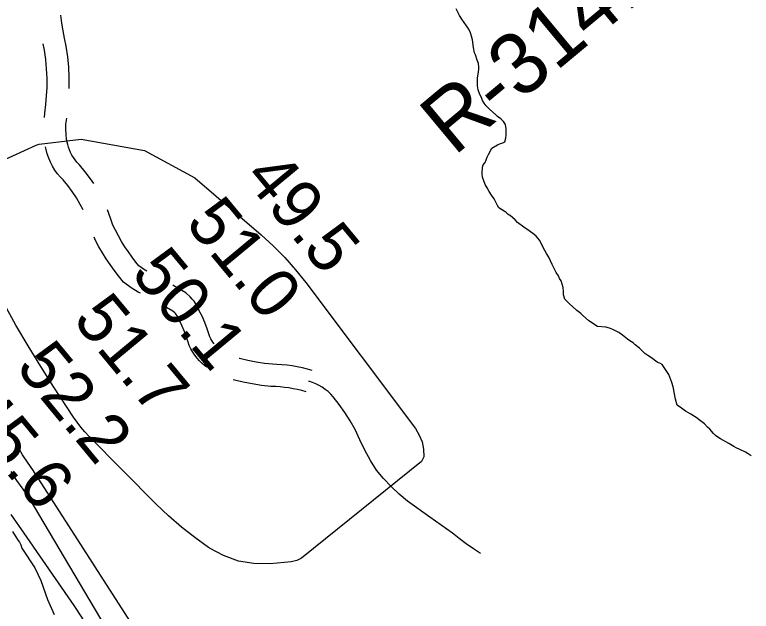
# Model space of a CAD drawing. Extents: x 3172231 to 3210228, y 940198 to 965780.
# Drawn here: x 3193133 to 3194127, y 949300 to 950105 of the extents above; entities that cross this region are included whole.
import ezdxf

# ---------------------------------------------------------------- set-up
doc = ezdxf.new("R2010")
doc.units = 0
for name, color, linetype in [('V-RIVR-RANG', 7, 'Continuous'), ('V-RIVR-RANG-IDEN', 7, 'Continuous'), ('V-ROAD-CNTR', 7, 'Continuous'), ('V-SITE-VEGE', 7, 'Continuous'), ('V-TOPO-MAJR', 7, 'Continuous'), ('V-TOPO-MINR', 7, 'Continuous'), ('V-TOPO-SHOR', 7, 'Continuous')]:
    doc.layers.add(name, color=color, linetype=linetype)

msp = doc.modelspace()

# ---------------------------------------------------------------- linework, layer by layer
at = {"layer": 'V-ROAD-CNTR'}
msp.add_line((3193530.228, 949610.409), (3193530.496, 949610.682), dxfattribs=at)
for points in [[(3193206.692, 950005.414), (3193206.723, 950005.915), (3193206.802, 950020.088), (3193206.17, 950034.215), (3193204.829, 950048.292), (3193202.766, 950062.391), (3193200.442, 950073.172), (3193198.525, 950083.326), (3193196.875, 950093.525), (3193195.407, 950104.369), (3193195.377, 950104.524)], [(3193173.183, 949966.436), (3193173.862, 949972.058), (3193175.047, 949983.761), (3193176.009, 949995.485), (3193176.729, 950006.939), (3193176.798, 950019.5), (3193176.234, 950032.121), (3193175.035, 950044.696), (3193173.228, 950057.053), (3193171.327, 950065.869)], [(3193239.748, 949877.047), (3193235.422, 949883.609), (3193228.336, 949893.167), (3193220.637, 949902.442), (3193217.138, 949906.013), (3193214.638, 949908.962), (3193212.352, 949912.103), (3193210.293, 949915.414), (3193208.486, 949918.866), (3193206.943, 949922.428), (3193205.671, 949926.08), (3193204.648, 949929.886), (3193203.223, 949936.76), (3193202.367, 949943.59), (3193202.058, 949950.465), (3193202.296, 949957.277), (3193203.296, 949965.566)], [(3193225.366, 949841.717), (3193221.681, 949848.925), (3193216.492, 949857.819), (3193210.83, 949866.405), (3193204.726, 949874.639), (3193198.343, 949882.33), (3193194.954, 949885.789), (3193191.038, 949890.408), (3193187.452, 949895.333), (3193184.231, 949900.516), (3193181.396, 949905.928), (3193178.975, 949911.52), (3193176.983, 949917.24), (3193175.45, 949922.942), (3193174.675, 949926.682)], [(3193311.262, 949758.985), (3193307.037, 949761.604), (3193300.844, 949766.014), (3193296.6, 949771.212), (3193291.439, 949777.961), (3193286.494, 949784.882), (3193281.77, 949791.963), (3193277.276, 949799.19), (3193273.02, 949806.556), (3193269.005, 949814.049), (3193265.639, 949820.843), (3193262.519, 949830.653), (3193258.328, 949841.69)], [(3193302.874, 949729.147), (3193299.828, 949730.776), (3193290.415, 949736.612), (3193280.158, 949743.916), (3193273.06, 949752.608), (3193267.313, 949760.125), (3193261.806, 949767.832), (3193256.548, 949775.713), (3193251.544, 949783.76), (3193246.804, 949791.964), (3193242.337, 949800.301), (3193240.189, 949804.636)], [(3193402.084, 949660.99), (3193400.431, 949663.108), (3193398.924, 949665.378), (3193397.601, 949667.751), (3193396.466, 949670.207), (3193395.462, 949672.903), (3193392.887, 949680.99), (3193389.643, 949689.647), (3193385.963, 949698.124), (3193382.261, 949705.605), (3193381.176, 949708.225), (3193379.438, 949711.705), (3193377.448, 949715.072), (3193375.217, 949718.297), (3193372.76, 949721.357), (3193369.92, 949724.416), (3193364.013, 949729.564), (3193347.907, 949738.961), (3193346.354, 949739.879)], [(3193392.317, 949629.347), (3193389.392, 949631.881), (3193386.188, 949634.466), (3193382.556, 949637.881), (3193379.17, 949641.589), (3193376.073, 949645.558), (3193373.288, 949649.752), (3193370.843, 949654.137), (3193368.754, 949658.661), (3193367.096, 949663.107), (3193364.529, 949671.17), (3193361.819, 949678.403), (3193358.743, 949685.49), (3193354.929, 949693.197), (3193353.864, 949695.767), (3193353.072, 949697.353), (3193352.166, 949698.886), (3193351.153, 949700.351), (3193350.042, 949701.735), (3193349.014, 949702.842), (3193346.443, 949705.082), (3193337.962, 949710.03)], [(3193534.479, 949625.144), (3193528.044, 949626.916), (3193521.296, 949628.528), (3193514.486, 949629.912), (3193507.625, 949631.061), (3193500.733, 949631.973), (3193493.819, 949632.65), (3193486.891, 949633.088), (3193480.907, 949633.262), (3193470.087, 949634.572), (3193458.894, 949636.332), (3193447.772, 949638.485), (3193436.341, 949641.121), (3193435.984, 949641.196)], [(3193526.513, 949596.22), (3193520.574, 949597.856), (3193514.82, 949599.23), (3193509.02, 949600.41), (3193503.179, 949601.387), (3193497.303, 949602.165), (3193491.409, 949602.742), (3193485.509, 949603.116), (3193478.663, 949603.314), (3193465.953, 949604.854), (3193453.712, 949606.778), (3193441.548, 949609.133), (3193429.883, 949611.823), (3193428.007, 949612.217)], [(3193761.94, 949377.927), (3193752.071, 949384.335), (3193742.433, 949391.095), (3193733.043, 949398.198), (3193723.919, 949405.626), (3193693.39, 949426.931), (3193663.182, 949448.693), (3193651.932, 949458.272), (3193641.176, 949468.428), (3193630.954, 949479.126), (3193621.312, 949490.321), (3193613.266, 949503.659), (3193605.77, 949517.332), (3193598.848, 949531.303), (3193592.516, 949545.539), (3193585.876, 949556.983), (3193578.732, 949568.137), (3193571.104, 949578.964), (3193563.016, 949589.436), (3193559.698, 949593.026), (3193556.1, 949596.391), (3193552.246, 949599.502), (3193548.162, 949602.33), (3193543.884, 949604.851), (3193539.442, 949607.047), (3193534.879, 949608.902), (3193530.228, 949610.409)]]:
    msp.add_lwpolyline(points, dxfattribs=at)
at = {"layer": 'V-SITE-VEGE'}
for p, q in [((3193733.58, 950103.813), (3193728.669, 950112.724)), ((3193736.379, 950099.013), (3193733.58, 950103.813)), ((3193745.812, 950085.318), (3193736.379, 950099.013)), ((3193748.268, 950080.517), (3193745.812, 950085.318)), ((3193749.689, 950076.051), (3193748.268, 950080.517)), ((3193750.769, 950071.238), (3193749.689, 950076.051)), ((3193752.245, 950060.57), (3193750.769, 950071.238)), ((3193753.687, 950053.691), (3193752.245, 950060.57)), ((3193755.092, 950050.946), (3193753.687, 950053.691)), ((3193757.228, 950043.731), (3193755.092, 950050.946)), ((3193758.995, 950038.921), (3193757.228, 950043.731)), ((3193759.378, 950034.792), (3193758.995, 950038.921)), ((3193759.098, 950027.896), (3193759.409, 950031.345)), ((3193759.409, 950031.345), (3193759.378, 950034.792)), ((3193757.799, 950019.272), (3193759.098, 950027.896)), ((3193757.521, 950012.376), (3193757.832, 950015.825)), ((3193757.552, 950008.932), (3193757.521, 950012.376)), ((3193757.832, 950015.825), (3193757.799, 950019.272)), ((3193758.635, 950003.773), (3193757.552, 950008.932)), ((3193760.763, 949997.246), (3193758.635, 950003.773)), ((3193762.868, 949993.129), (3193760.763, 949997.246)), ((3193764.629, 949989.013), (3193762.868, 949993.129)), ((3193766.729, 949985.584), (3193764.629, 949989.013)), ((3193769.174, 949982.162), (3193766.729, 949985.584)), ((3193774.042, 949977.384), (3193769.174, 949982.162)), ((3193782.382, 949969.88), (3193774.042, 949977.384)), ((3193784.817, 949967.492), (3193782.382, 949969.88)), ((3193789.326, 949964.433), (3193784.817, 949967.492)), ((3193792.802, 949961.019), (3193789.326, 949964.433)), ((3193795.597, 949956.91), (3193792.802, 949961.019)), ((3193796.341, 949951.059), (3193795.597, 949956.91)), ((3193796.419, 949942.789), (3193796.341, 949951.059)), ((3193795.771, 949938.304), (3193796.419, 949942.789)), ((3193784.485, 949929.24), (3193788.603, 949931.003)), ((3193788.603, 949931.003), (3193791.694, 949932.064)), ((3193791.694, 949932.064), (3193794.438, 949933.467)), ((3193794.438, 949933.467), (3193795.771, 949938.304)), ((3193772.883, 949917.071), (3193776.946, 949924.689)), ((3193776.946, 949924.689), (3193784.485, 949929.24)), ((3193767.82, 949905.653), (3193770.853, 949912.917)), ((3193770.853, 949912.917), (3193772.883, 949917.071)), ((3193764.437, 949899.075), (3193765.436, 949902.53)), ((3193765.436, 949902.53), (3193767.82, 949905.653)), ((3193764.175, 949890.113), (3193764.437, 949899.075)), ((3193764.218, 949885.634), (3193764.175, 949890.113)), ((3193768.101, 949875.677), (3193764.218, 949885.634)), ((3193770.55, 949871.564), (3193768.101, 949875.677)), ((3193773.356, 949866.424), (3193770.55, 949871.564)), ((3193776.504, 949861.283), (3193773.356, 949866.424)), ((3193779.996, 949856.493), (3193776.504, 949861.283)), ((3193784.559, 949847.576), (3193779.996, 949856.493)), ((3193786.31, 949844.49), (3193784.559, 949847.576)), ((3193793.586, 949840.08), (3193786.31, 949844.49)), ((3193796.361, 949838.036), (3193793.586, 949840.08)), ((3193798.796, 949835.648), (3193796.361, 949838.036)), ((3193801.569, 949833.951), (3193798.796, 949835.648)), ((3193808.514, 949828.159), (3193801.569, 949833.951)), ((3193811.647, 949824.741), (3193808.514, 949828.159)), ((3193820.323, 949818.275), (3193811.647, 949824.741)), ((3193827.603, 949813.52), (3193820.323, 949818.275)), ((3193834.2, 949808.412), (3193827.603, 949813.52)), ((3193836.979, 949806.026), (3193834.2, 949808.412)), ((3193841.505, 949800.9), (3193836.979, 949806.026)), ((3193844.661, 949795.071), (3193841.505, 949800.9)), ((3193846.422, 949790.953), (3193844.661, 949795.071)), ((3193850.977, 949782.726), (3193846.422, 949790.953)), ((3193854.123, 949777.932), (3193850.977, 949782.726)), ((3193858.352, 949767.976), (3193854.123, 949777.932)), ((3193863.62, 949757.345), (3193858.352, 949767.976)), ((3193866.765, 949752.551), (3193863.62, 949757.345)), ((3193868.52, 949749.12), (3193866.765, 949752.551)), ((3193870.622, 949745.694), (3193868.52, 949749.12)), ((3193873.116, 949736.759), (3193870.622, 949745.694)), ((3193873.509, 949731.594), (3193873.116, 949736.759)), ((3193873.55, 949727.115), (3193873.509, 949731.594)), ((3193875.326, 949721.276), (3193873.55, 949727.115)), ((3193881.591, 949715.132), (3193875.326, 949721.276)), ((3193891.667, 949705.92), (3193881.591, 949715.132)), ((3193897.217, 949701.836), (3193891.667, 949705.92)), ((3193899.308, 949699.446), (3193897.217, 949701.836)), ((3193907.994, 949691.944), (3193899.308, 949699.446)), ((3193919.778, 949684.473), (3193907.994, 949691.944)), ((3193930.816, 949683.197), (3193919.778, 949684.473)), ((3193935.65, 949682.21), (3193930.816, 949683.197)), ((3193940.149, 949680.185), (3193935.65, 949682.21)), ((3193948.456, 949676.128), (3193940.149, 949680.185)), ((3193953.312, 949672.728), (3193948.456, 949676.128)), ((3193960.254, 949667.278), (3193953.312, 949672.728)), ((3193963.034, 949664.892), (3193960.254, 949667.278)), ((3193967.539, 949662.177), (3193963.034, 949664.892)), ((3193970.662, 949659.451), (3193967.539, 949662.177)), ((3193976.221, 949655.023), (3193970.662, 949659.451)), ((3193983.524, 949647.857), (3193976.221, 949655.023)), ((3193987.339, 949645.133), (3193983.524, 949647.857)), ((3193992.535, 949642.082), (3193987.339, 949645.133)), ((3194000.172, 949636.294), (3193992.535, 949642.082)), ((3194001.903, 949635.276), (3194000.172, 949636.294)), ((3194003.629, 949634.948), (3194001.903, 949635.276)), ((3194006.748, 949632.911), (3194003.629, 949634.948)), ((3194015.833, 949619.558), (3194006.748, 949632.911)), ((3194020.068, 949608.914), (3194015.833, 949619.558)), ((3194021.848, 949602.727), (3194020.068, 949608.914)), ((3194024.756, 949586.214), (3194021.848, 949602.727)), ((3194026.9, 949578.311), (3194024.756, 949586.214)), ((3194033.141, 949574.233), (3194026.9, 949578.311)), ((3194038.349, 949570.148), (3194033.141, 949574.233)), ((3194041.468, 949568.108), (3194038.349, 949570.148)), ((3194045.621, 949566.08), (3194041.468, 949568.108)), ((3194053.942, 949560.645), (3194045.621, 949566.08)), ((3194056.721, 949558.257), (3194053.942, 949560.645)), ((3194060.537, 949555.537), (3194056.721, 949558.257)), ((3194064.008, 949552.813), (3194060.537, 949555.537)), ((3194068.184, 949548.371), (3194064.008, 949552.813)), ((3194071.311, 949545.645), (3194068.184, 949548.371)), ((3194076.19, 949539.833), (3194071.311, 949545.645)), ((3194078.969, 949537.447), (3194076.19, 949539.833)), ((3194082.092, 949535.063), (3194078.969, 949537.447)), ((3194085.563, 949532.684), (3194082.092, 949535.063)), ((3194096.643, 949526.585), (3194085.563, 949532.684)), ((3194103.578, 949522.169), (3194096.643, 949526.585)), ((3194106.695, 949520.476), (3194103.578, 949522.169)), ((3194111.534, 949518.454), (3194106.695, 949520.476)), ((3194119.153, 949514.735), (3194111.534, 949518.454)), ((3194122.962, 949512.703), (3194119.153, 949514.735)), ((3194127.125, 949509.642), (3194122.962, 949512.703)), ((3193129.971, 949407.518), (3193133.782, 949401.808)), ((3193133.782, 949401.808), (3193137.593, 949395.656)), ((3193137.593, 949395.656), (3193139.387, 949393.244)), ((3193139.387, 949393.244), (3193141.407, 949389.727)), ((3193141.407, 949389.727), (3193142.552, 949385.32)), ((3193142.552, 949385.32), (3193160.433, 949358.52)), ((3193160.433, 949358.52), (3193168.422, 949341.417)), ((3193168.422, 949341.417), (3193177.456, 949316.038)), ((3193177.456, 949316.038), (3193186.34, 949295.861))]:
    msp.add_line(p, q, dxfattribs=at)
at = {"layer": 'V-TOPO-MAJR'}
msp.add_lwpolyline([(3193516.705, 948838.904), (3193152.618, 949453.266), (3193144.372, 949464.933), (3193136.2, 949476.651), (3193128.142, 949488.448)], dxfattribs=at)
at = {"layer": 'V-TOPO-MINR'}
for points in [[(3193662.332, 948705.821), (3193157.503, 949490.958), (3193155.17, 949494.205), (3193154.408, 949495.298), (3193145.455, 949508.28), (3193143.601, 949511.145), (3193141.865, 949514.074), (3193140.304, 949517.101), (3193138.86, 949520.193), (3193137.489, 949523.327), (3193136.096, 949526.451), (3192725.506, 950276.216)], [(3193114.836, 949907.197), (3193161.924, 949929.04), (3193165.953, 949930.315), (3193222.862, 949936.819), (3193308.474, 949921.775), (3193376.184, 949884.845), (3193465.737, 949808.078), (3193482.048, 949793.139), (3193497.657, 949777.541), (3193512.211, 949760.954), (3193526.061, 949743.708), (3193673.877, 949546.748), (3193679.108, 949537.893), (3193682.951, 949528.63), (3193684.71, 949518.758), (3193685.08, 949508.48), (3193682.14, 949502.158), (3193520.16, 949371.71), (3193513.658, 949368.646), (3193506.332, 949366.801), (3193477.805, 949364.294), (3193456.048, 949364.653), (3193435.017, 949367.825), (3193415.073, 949375.218), (3193395.855, 949385.423), (3193394.822, 949386.119), (3193376.123, 949399.525), (3193358.002, 949413.63), (3193340.749, 949428.783), (3193324.074, 949444.636), (3193233.712, 949535.795), (3193227.914, 949542.011), (3193222.383, 949548.443), (3193217.251, 949555.198), (3193212.386, 949562.169), (3193185.935, 949602.633), (3193168.37, 949630.194), (3193151.237, 949658.014), (3193134.752, 949686.222), (3193118.699, 949714.69)], [(3193132.361, 949047.169), (3193157.962, 949035.837), (3193182.711, 949022.169), (3193212.498, 949003.006), (3193232.211, 948991.879), (3193252.563, 948982.352), (3193273.875, 948975.224), (3193295.827, 948969.696), (3193309.683, 948972.386), (3193319.522, 948978.339), (3193323.337, 948989.188), (3193323.135, 949003.301), (3193316.239, 949019.847), (3193264.141, 949206.888), (3193257.773, 949224.633), (3193250.581, 949242.114), (3193242.316, 949259.14), (3193233.457, 949275.831), (3193223.708, 949292.018), (3193213.365, 949307.869), (3193145.795, 949405.528), (3193128.55, 949430.715)]]:
    msp.add_lwpolyline(points, dxfattribs=at)
at = {"layer": 'V-TOPO-SHOR'}
for points in [[(3193907.994, 949691.944), (3193899.308, 949699.444), (3193897.217, 949701.836), (3193891.667, 949705.92), (3193881.589, 949715.13), (3193875.328, 949721.274), (3193873.55, 949727.115), (3193873.509, 949731.594), (3193873.116, 949736.759), (3193870.622, 949745.694), (3193868.52, 949749.12), (3193866.765, 949752.551), (3193863.62, 949757.345), (3193858.352, 949767.976), (3193854.125, 949777.932), (3193850.977, 949782.726), (3193846.422, 949790.953), (3193844.661, 949795.071), (3193841.505, 949800.9), (3193836.977, 949806.026), (3193834.2, 949808.412), (3193827.603, 949813.52), (3193820.323, 949818.275), (3193811.647, 949824.741), (3193808.514, 949828.159), (3193801.569, 949833.951), (3193800.529, 949834.631), (3193798.796, 949835.648), (3193796.363, 949838.036), (3193793.586, 949840.078), (3193786.31, 949844.49), (3193784.559, 949847.576), (3193779.996, 949856.493), (3193776.504, 949861.283), (3193773.356, 949866.424), (3193770.55, 949871.564), (3193768.101, 949875.677), (3193764.218, 949885.634), (3193764.175, 949890.113), (3193764.437, 949899.075), (3193765.436, 949902.53), (3193767.82, 949905.653), (3193770.853, 949912.917), (3193772.883, 949917.071), (3193776.946, 949924.689), (3193784.485, 949929.24), (3193788.603, 949931.001), (3193791.694, 949932.064), (3193794.438, 949933.467), (3193795.771, 949938.304), (3193796.419, 949942.789), (3193796.341, 949951.059), (3193795.597, 949956.91), (3193792.802, 949961.019), (3193789.324, 949964.433), (3193784.817, 949967.492), (3193782.382, 949969.88), (3193774.042, 949977.384), (3193769.174, 949982.162), (3193766.729, 949985.584), (3193764.629, 949989.013), (3193762.868, 949993.129), (3193760.763, 949997.246), (3193758.635, 950003.773), (3193757.552, 950008.932), (3193757.521, 950012.376), (3193757.832, 950015.825), (3193757.799, 950019.27), (3193759.098, 950027.896), (3193759.409, 950031.345), (3193759.378, 950034.792), (3193758.995, 950038.923), (3193757.228, 950043.731), (3193755.092, 950050.946), (3193753.687, 950053.691), (3193752.245, 950060.57), (3193750.767, 950071.238), (3193749.689, 950076.051), (3193748.268, 950080.517), (3193745.812, 950085.318), (3193736.379, 950099.013), (3193733.58, 950103.811), (3193728.671, 950112.724)], [(3194127.125, 949509.642), (3194122.962, 949512.703), (3194119.153, 949514.735), (3194111.536, 949518.454), (3194106.695, 949520.476), (3194103.578, 949522.169), (3194096.643, 949526.585), (3194085.561, 949532.684), (3194082.092, 949535.063), (3194078.969, 949537.447), (3194076.19, 949539.833), (3194071.311, 949545.645), (3194068.184, 949548.371), (3194064.008, 949552.813), (3194060.537, 949555.537), (3194056.721, 949558.257), (3194053.942, 949560.645), (3194045.621, 949566.08), (3194041.468, 949568.108), (3194038.349, 949570.148), (3194033.141, 949574.233), (3194026.9, 949578.311), (3194024.758, 949586.214), (3194021.848, 949602.727), (3194020.068, 949608.914), (3194015.833, 949619.556), (3194006.748, 949632.911), (3194003.629, 949634.948), (3194001.903, 949635.276), (3194000.172, 949636.294), (3193992.535, 949642.082), (3193987.339, 949645.133), (3193983.524, 949647.855), (3193976.221, 949655.023), (3193970.664, 949659.451), (3193967.539, 949662.177), (3193963.034, 949664.892), (3193960.254, 949667.278), (3193953.312, 949672.728), (3193948.456, 949676.128), (3193940.149, 949680.185), (3193935.65, 949682.21), (3193930.816, 949683.197), (3193919.778, 949684.473), (3193907.994, 949691.944)]]:
    msp.add_lwpolyline(points, dxfattribs=at)

# ---------------------------------------------------------------- texts
at = {"layer": 'V-RIVR-RANG'}
for s, p in [('49.5', (3193440.636, 949884.821)), ('51.0', (3193361.946, 949823.057)), ('50.1', (3193288.472, 949754.998)), ('51.7', (3193210.118, 949692.828)), ('52.2', (3193133.278, 949628.83)), ('45.6', (3193055.261, 949566.254))]:
    msp.add_text(s, height=67, rotation=309.648326, dxfattribs=at).set_placement(p)
at = {"layer": 'V-RIVR-RANG-IDEN'}
msp.add_text('R-314.45', height=82.9998, rotation=39.790127, dxfattribs=at).set_placement((3193725.963, 949913.263))

doc.saveas('drawing.dxf')
